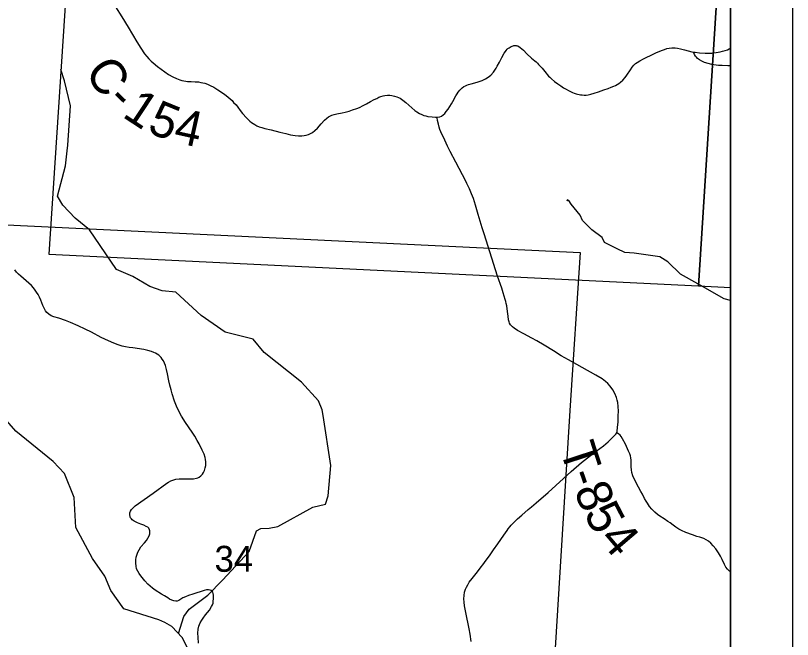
# Model space of a CAD drawing. Extents: x 0 to 34, y 0 to 22.
# Drawn here: x 29.485 to 30.737, y 17.697 to 18.702 of the extents above; entities that cross this region are included whole.
import ezdxf

# ---------------------------------------------------------------- set-up
doc = ezdxf.new("R2010")
doc.units = 0
for name, color, linetype in [('GM_X_County_Road', 7, 'Continuous'), ('GM_X_County_Road_Text', 7, 'Continuous'), ('GM_X_County_Text', 7, 'Continuous'), ('GM_X_Minor_River', 7, 'Continuous'), ('GM_X_Section', 7, 'Continuous'), ('GM_X_Section_Text', 7, 'Continuous'), ('GM_X_State_Shield', 7, 'Continuous'), ('GM_X_Township_Road', 7, 'Continuous'), ('GM_X_Township_Road_Text', 7, 'Continuous'), ('SH_Cut_Line', 7, 'Continuous'), ('SH_Data', 7, 'Continuous')]:
    doc.layers.add(name, color=color, linetype=linetype)

msp = doc.modelspace()

# ---------------------------------------------------------------- linework, layer by layer
at = {"layer": 'GM_X_County_Road'}
for points in [[(29.6461, 18.7166), (29.6563, 18.7004), (29.6668, 18.6835), (29.6739, 18.6718), (29.6808, 18.66), (29.687, 18.65), (29.6933, 18.6407), (29.6967, 18.6364), (29.7002, 18.6325), (29.7036, 18.6289), (29.7068, 18.626), (29.714, 18.6204), (29.7197, 18.6161), (29.732, 18.6077), (29.7389, 18.6037), (29.7444, 18.601), (29.7501, 18.5987), (29.7533, 18.5978), (29.7563, 18.5972), (29.7595, 18.5967), (29.7625, 18.5964), (29.7683, 18.5961), (29.7749, 18.5958), (29.7801, 18.5954), (29.7836, 18.5948), (29.787, 18.5942), (29.7905, 18.5933), (29.7946, 18.5917), (29.7991, 18.5896), (29.8046, 18.5868), (29.8111, 18.583), (29.8219, 18.5756), (29.8279, 18.5708), (29.8341, 18.5654), (29.8367, 18.5625), (29.8406, 18.5585), (29.8435, 18.5548), (29.8472, 18.5496), (29.8511, 18.5445), (29.8572, 18.5374), (29.8599, 18.5348), (29.8628, 18.5322), (29.8655, 18.53), (29.8706, 18.5266), (29.8741, 18.5248), (29.878, 18.5233), (29.8822, 18.5219), (29.8871, 18.5206), (29.8971, 18.5182), (29.9109, 18.5147), (29.9208, 18.5121), (29.9285, 18.5102), (29.9321, 18.5095), (29.9361, 18.5089), (29.9412, 18.5086), (29.9466, 18.5086), (29.9502, 18.509), (29.9538, 18.5097), (29.9573, 18.5109), (29.9604, 18.5122), (29.9637, 18.5141), (29.9676, 18.5171), (29.9719, 18.5212), (29.978, 18.5279), (29.983, 18.5336), (29.9867, 18.537), (29.9894, 18.5391), (29.9919, 18.5405), (29.995, 18.5418), (29.9986, 18.5429), (30.0032, 18.5438), (30.0114, 18.5455), (30.0165, 18.5467), (30.0227, 18.5484), (30.0285, 18.5504), (30.035, 18.5527), (30.0393, 18.5545), (30.0454, 18.5573), (30.0509, 18.5602), (30.0575, 18.5638), (30.0632, 18.5669), (30.0672, 18.569), (30.0706, 18.5708), (30.0738, 18.5722), (30.0775, 18.5732), (30.0806, 18.5738), (30.0844, 18.5742), (30.0883, 18.5742), (30.0918, 18.5737), (30.0957, 18.5728), (30.0997, 18.5716), (30.1022, 18.5706), (30.1049, 18.5691), (30.1095, 18.5661), (30.1142, 18.5624), (30.1238, 18.5536), (30.1288, 18.5495), (30.1321, 18.5472), (30.136, 18.5447), (30.1399, 18.5428), (30.1433, 18.5415), (30.1464, 18.5406), (30.1499, 18.5399), (30.1566, 18.539), (30.1621, 18.5385), (30.1645, 18.5386)], [(30.1645, 18.5386), (30.1653, 18.5386), (30.169, 18.5394), (30.1715, 18.5405), (30.1742, 18.5422), (30.1768, 18.5446), (30.1794, 18.5476), (30.1824, 18.5516), (30.1852, 18.5559), (30.1877, 18.56), (30.1899, 18.5637), (30.1947, 18.5729), (30.1968, 18.5761), (30.1987, 18.5792), (30.201, 18.582), (30.2031, 18.5842), (30.2052, 18.5861), (30.2079, 18.588), (30.2102, 18.5893), (30.2124, 18.5902), (30.2152, 18.5911), (30.2197, 18.5925), (30.2253, 18.594), (30.2307, 18.5955), (30.237, 18.5979), (30.2425, 18.6006), (30.2466, 18.6031), (30.2509, 18.6065), (30.2555, 18.6114), (30.2596, 18.6174), (30.2615, 18.6209), (30.265, 18.6272), (30.2689, 18.6348), (30.2728, 18.6419), (30.2747, 18.6447), (30.276, 18.6464), (30.2775, 18.6482), (30.2788, 18.6493), (30.2805, 18.6507), (30.2821, 18.6517), (30.2838, 18.6527), (30.2853, 18.6533), (30.2869, 18.6538), (30.2882, 18.654), (30.2896, 18.6541), (30.2907, 18.6541), (30.2918, 18.6541), (30.2932, 18.6539), (30.2947, 18.6534), (30.2964, 18.6525), (30.2983, 18.6512), (30.3009, 18.6489), (30.3037, 18.6465), (30.3094, 18.6406), (30.3168, 18.634), (30.3221, 18.6294), (30.3241, 18.6278), (30.3262, 18.6257), (30.3282, 18.6238), (30.3311, 18.6206), (30.3339, 18.6176), (30.3384, 18.6121), (30.3443, 18.6049), (30.3461, 18.603), (30.349, 18.6003), (30.3536, 18.5964), (30.359, 18.5923), (30.3638, 18.5891), (30.3682, 18.5862), (30.3725, 18.5837), (30.3763, 18.5817), (30.3829, 18.5785), (30.3857, 18.5774), (30.3886, 18.5765), (30.3908, 18.5758), (30.3934, 18.5753), (30.3959, 18.5749), (30.3986, 18.5747), (30.4016, 18.5744), (30.4047, 18.5744), (30.4081, 18.5747), (30.4102, 18.5751), (30.4125, 18.5756), (30.4179, 18.5773), (30.4247, 18.5796), (30.4334, 18.5826), (30.4403, 18.5851), (30.4449, 18.5868), (30.4496, 18.5887), (30.452, 18.5898), (30.4547, 18.5913), (30.4574, 18.5929), (30.4599, 18.5949), (30.4639, 18.5984), (30.4675, 18.6025), (30.4705, 18.6064), (30.4763, 18.6151), (30.4789, 18.6191), (30.4815, 18.6225), (30.4845, 18.625), (30.487, 18.627), (30.4912, 18.6295), (30.4972, 18.6326), (30.5015, 18.6346), (30.5097, 18.6386), (30.517, 18.6422), (30.5262, 18.6462), (30.5312, 18.648), (30.5349, 18.6491), (30.5387, 18.6499), (30.5429, 18.6504), (30.548, 18.6502), (30.5517, 18.6498), (30.5569, 18.6488), (30.563, 18.6473), (30.5691, 18.6457), (30.575, 18.6442), (30.578, 18.6437), (30.5802, 18.6433), (30.5872, 18.6426), (30.5967, 18.642), (30.6013, 18.642), (30.6074, 18.6421), (30.6141, 18.6427), (30.6205, 18.6439), (30.6247, 18.6448), (30.6288, 18.6459), (30.6323, 18.6472), (30.6352, 18.6487), (30.6372, 18.6499)]]:
    msp.add_lwpolyline(points, dxfattribs=at)
at = {"layer": 'GM_X_County_Text'}
msp.add_lwpolyline([(29.4304, 15.2876), (29.5713, 15.2568), (29.7749, 15.1808), (30.0202, 15.1042), (30.4162, 15.0021), (30.5527, 14.9001), (30.6372, 14.8869), (30.6372, 20.3098), (29.547, 20.3639), (28.6062, 20.4055)], dxfattribs=at)
at = {"layer": 'GM_X_Minor_River'}
for points in [[(29.7477, 17.7063), (29.7563, 17.7339), (29.765, 17.7458), (29.7951, 17.7684), (29.8189, 17.7927), (29.8615, 17.8384), (29.8735, 17.8722), (29.8804, 17.8758), (29.8937, 17.8765), (29.9077, 17.8787), (29.9642, 17.9103), (29.9848, 17.915), (29.989, 17.9285), (29.9935, 17.9773), (29.9808, 18.0579), (29.9792, 18.067), (29.9732, 18.0813), (29.9458, 18.1118), (29.886, 18.1596), (29.8681, 18.1811), (29.8231, 18.192), (29.7842, 18.2191), (29.7434, 18.2564), (29.7216, 18.259), (29.7014, 18.2657), (29.6742, 18.2818), (29.6481, 18.2933), (29.6047, 18.3573), (29.5815, 18.3759), (29.5617, 18.397), (29.5527, 18.4114), (29.5659, 18.4603), (29.5685, 18.4845), (29.5695, 18.4936), (29.5737, 18.5569), (29.564, 18.5971), (29.5585, 18.6155)], [(30.6372, 18.2433), (30.6271, 18.2459), (30.5847, 18.2701), (30.5567, 18.2856), (30.5363, 18.3053), (30.5234, 18.3137), (30.4822, 18.3197), (30.4671, 18.3208), (30.455, 18.3264), (30.4505, 18.3287), (30.4342, 18.3366), (30.4304, 18.345), (30.4141, 18.3571), (30.399, 18.3719), (30.3952, 18.381), (30.3808, 18.3985), (30.377, 18.4045), (30.3744, 18.4038), (30.3755, 18.4064)], [(29.7666, 17.6748), (29.7537, 17.6999), (29.7373, 17.7175), (29.7257, 17.7243), (29.7164, 17.7284), (29.6599, 17.7461), (29.6389, 17.7757), (29.6293, 17.7988), (29.6094, 17.8275), (29.5822, 17.8773), (29.5795, 17.9256), (29.5644, 17.9641), (29.5458, 17.9837), (29.486, 18.0327), (29.4484, 18.0749)]]:
    msp.add_lwpolyline(points, dxfattribs=at)
at = {"layer": 'GM_X_Section'}
msp.add_lwpolyline([(30.3951, 18.3204), (30.3786, 18.0661), (30.3627, 17.8138), (30.3475, 17.5607), (30.331, 17.3066), (30.2563, 17.3105), (30.177, 17.3146), (30.0998, 17.3186), (30.0187, 17.3227), (29.9382, 17.3269), (29.8591, 17.3308), (29.7781, 17.3351), (29.6912, 17.3401), (29.6192, 17.3436), (29.5335, 17.3481), (29.4508, 17.3523), (29.3695, 17.3565), (29.2849, 17.3606), (29.3481, 18.3713)], close=True, dxfattribs=at)
at = {"layer": 'GM_X_State_Shield'}
for points in [[(30.6372, 19.0797), (30.6372, 19.3091), (29.6072, 19.3563), (29.5388, 18.3179), (30.5859, 18.267)], [(30.6372, 18.2643), (30.6372, 19.0797), (30.5859, 18.267)]]:
    msp.add_lwpolyline(points, close=True, dxfattribs=at)
at = {"layer": 'GM_X_Township_Road'}
for points in [[(30.6372, 18.6214), (30.633, 18.6214), (30.6237, 18.6219), (30.6182, 18.6222), (30.6141, 18.6226), (30.6074, 18.6236), (30.6014, 18.625), (30.5956, 18.6269), (30.5911, 18.629), (30.5875, 18.6313), (30.5843, 18.6335), (30.5824, 18.6352), (30.581, 18.637), (30.5796, 18.6396), (30.578, 18.6437)], [(30.2775, 17.8726), (30.2793, 17.8752), (30.282, 17.8786), (30.284, 17.8809), (30.2865, 17.8837), (30.2908, 17.8882), (30.2939, 17.8912), (30.301, 17.8973), (30.3114, 17.9061), (30.3166, 17.9105), (30.3241, 17.917), (30.3433, 17.9338), (30.3808, 17.9674), (30.3975, 17.9821), (30.4071, 17.9896), (30.4211, 18.0004), (30.4325, 18.009), (30.4402, 18.0153), (30.4446, 18.0196), (30.4495, 18.0246), (30.4524, 18.0279), (30.4542, 18.0301), (30.4548, 18.0327), (30.4554, 18.0383), (30.4561, 18.0475), (30.4566, 18.0571), (30.4569, 18.065), (30.4565, 18.0721), (30.4557, 18.0787), (30.4548, 18.0828), (30.4535, 18.0868), (30.4509, 18.0933), (30.4477, 18.0994), (30.4436, 18.105), (30.4399, 18.1092), (30.4359, 18.1129), (30.4303, 18.1168), (30.4204, 18.123), (30.3982, 18.1354), (30.3897, 18.1401), (30.3761, 18.1475), (30.3645, 18.1542), (30.3519, 18.162), (30.337, 18.1711), (30.3253, 18.178), (30.3171, 18.1825), (30.3046, 18.1892), (30.2942, 18.1948), (30.2887, 18.1985), (30.2859, 18.2005), (30.2829, 18.2038), (30.2812, 18.2065), (30.2805, 18.2089), (30.2798, 18.2123), (30.279, 18.2177), (30.278, 18.2256), (30.2767, 18.2345), (30.276, 18.2384), (30.2753, 18.2418), (30.2744, 18.2449), (30.2727, 18.2504), (30.271, 18.2557), (30.2687, 18.2629), (30.262, 18.2824), (30.2402, 18.3504), (30.2371, 18.3602), (30.2308, 18.3816), (30.2264, 18.3968), (30.223, 18.4078), (30.2202, 18.4149), (30.2167, 18.423), (30.2124, 18.432), (30.2086, 18.4396), (30.2056, 18.4456), (30.195, 18.4661), (30.1858, 18.4834), (30.1815, 18.4922), (30.1769, 18.5016), (30.1708, 18.515), (30.1692, 18.5189), (30.168, 18.5225), (30.1668, 18.5272), (30.1654, 18.5335), (30.1647, 18.5376), (30.1645, 18.5386)], [(29.7803, 17.6907), (29.7794, 17.7006), (29.7792, 17.7072), (29.7795, 17.7135), (29.7806, 17.7183), (29.7815, 17.721), (29.7828, 17.7237), (29.7853, 17.728), (29.7876, 17.7312), (29.7915, 17.7364), (29.7977, 17.7443), (29.801, 17.75), (29.8028, 17.7529), (29.8035, 17.7553), (29.8039, 17.7583), (29.8042, 17.7627), (29.8043, 17.7664), (29.8041, 17.7684), (29.8038, 17.7709), (29.803, 17.773), (29.8019, 17.7746), (29.8006, 17.7757), (29.7991, 17.7764), (29.7961, 17.7769), (29.793, 17.7766), (29.7893, 17.7757), (29.771, 17.7701), (29.7642, 17.7676), (29.7591, 17.7657), (29.7548, 17.7639), (29.7482, 17.7596), (29.7458, 17.7587), (29.7433, 17.7584), (29.7402, 17.7589), (29.7371, 17.7601), (29.7332, 17.762), (29.7307, 17.7639), (29.7254, 17.7673), (29.7204, 17.7701), (29.7105, 17.7761), (29.7059, 17.7798), (29.6985, 17.7861), (29.6938, 17.7914), (29.6874, 17.7995), (29.6846, 17.8031), (29.6822, 17.8069), (29.6804, 17.8107), (29.6796, 17.8149), (29.6789, 17.8201), (29.6791, 17.8253), (29.6796, 17.8294), (29.6811, 17.8346), (29.6823, 17.8377), (29.6843, 17.8415), (29.6873, 17.8461), (29.6929, 17.8527), (29.6962, 17.8565), (29.6987, 17.8601), (29.7007, 17.864), (29.7016, 17.8669), (29.7019, 17.8695), (29.7016, 17.8719), (29.7012, 17.8738), (29.7001, 17.876), (29.6983, 17.8778), (29.696, 17.879), (29.6919, 17.8809), (29.6872, 17.8827), (29.682, 17.8846), (29.6763, 17.8876), (29.6731, 17.8899), (29.6719, 17.8913), (29.6707, 17.8927), (29.6699, 17.8947), (29.6695, 17.8982), (29.6697, 17.901), (29.6707, 17.9036), (29.6723, 17.9065), (29.6745, 17.9086), (29.6782, 17.9121), (29.7068, 17.9327), (29.7293, 17.9489), (29.7318, 17.9505), (29.7353, 17.9523), (29.7386, 17.9537), (29.7435, 17.9552), (29.749, 17.9558), (29.757, 17.9558), (29.7665, 17.9557), (29.7721, 17.9559), (29.7766, 17.9567), (29.7788, 17.9573), (29.781, 17.9585), (29.7841, 17.9607), (29.7865, 17.9634), (29.788, 17.9661), (29.7896, 17.9693), (29.791, 17.9735), (29.7917, 17.9775), (29.792, 17.9834), (29.7916, 17.9868), (29.7909, 17.9901), (29.7891, 17.9953), (29.7861, 18.0021), (29.7812, 18.0123), (29.7782, 18.0176), (29.7742, 18.0243), (29.7698, 18.0312), (29.7589, 18.0466), (29.7527, 18.0567), (29.7473, 18.0669), (29.7446, 18.0727), (29.7413, 18.0811), (29.7376, 18.0929), (29.7358, 18.0994), (29.734, 18.1066), (29.7325, 18.1136), (29.7303, 18.1248), (29.7287, 18.1321), (29.7269, 18.1382), (29.7253, 18.1423), (29.7235, 18.1457), (29.7215, 18.1489), (29.7197, 18.1513), (29.7162, 18.155), (29.7137, 18.1569), (29.711, 18.1585), (29.7083, 18.1596), (29.7046, 18.161), (29.6987, 18.1627), (29.6918, 18.1644), (29.6744, 18.1668), (29.6681, 18.1677), (29.6625, 18.1685), (29.6571, 18.1698), (29.6508, 18.1717), (29.6435, 18.1743), (29.6351, 18.178), (29.6232, 18.1837), (29.6079, 18.192), (29.5977, 18.1968), (29.5864, 18.2021), (29.5737, 18.2077), (29.5657, 18.2111), (29.5549, 18.2145), (29.5471, 18.2168), (29.5427, 18.2186), (29.5387, 18.2209), (29.5356, 18.2239), (29.5333, 18.2267), (29.5319, 18.2296), (29.5294, 18.2351), (29.5259, 18.2439), (29.5238, 18.2486), (29.5215, 18.2529), (29.5193, 18.2564), (29.5168, 18.2601), (29.5141, 18.2635), (29.5109, 18.2674), (29.5068, 18.2714), (29.5025, 18.2751), (29.4939, 18.2824), (29.4902, 18.2856), (29.4869, 18.2891), (29.4843, 18.2926)], [(30.6372, 17.8057), (30.6357, 17.8068), (30.6327, 17.8099), (30.6301, 17.8134), (30.6275, 17.8177), (30.6237, 17.8259), (30.6212, 17.8311), (30.6181, 17.8366), (30.6137, 17.843), (30.6096, 17.8479), (30.6058, 17.8522), (30.6018, 17.8554), (30.5983, 17.8577), (30.5945, 17.8594), (30.5914, 17.8606), (30.5879, 17.8616), (30.5832, 17.8628), (30.5761, 17.8655), (30.5654, 17.8695), (30.5585, 17.8724), (30.5539, 17.8747), (30.5493, 17.8778), (30.5448, 17.8811), (30.54, 17.8847), (30.5364, 17.8871), (30.5304, 17.8912), (30.5236, 17.8957), (30.5199, 17.8983), (30.5155, 17.902), (30.5106, 17.9071), (30.507, 17.9114), (30.5035, 17.9165), (30.5012, 17.92), (30.499, 17.9243), (30.4954, 17.9309), (30.4931, 17.9353), (30.4893, 17.9424), (30.4829, 17.9545), (30.4802, 17.9607), (30.4785, 17.966), (30.4778, 17.9703), (30.4774, 17.9752), (30.4773, 17.9814), (30.4771, 17.9857), (30.4768, 17.9895), (30.4761, 17.9926), (30.4749, 17.9961), (30.4732, 18.0004), (30.468, 18.0116), (30.4634, 18.02), (30.4614, 18.0239), (30.4596, 18.0264), (30.457, 18.0283), (30.4542, 18.0301)], [(30.2197, 17.6935), (30.2178, 17.7056), (30.2164, 17.7138), (30.2108, 17.7405), (30.2089, 17.7508), (30.208, 17.7568), (30.2077, 17.7622), (30.208, 17.7677), (30.2089, 17.7731), (30.2105, 17.7778), (30.212, 17.7814), (30.214, 17.785), (30.2165, 17.7891), (30.2209, 17.795), (30.2296, 17.8061), (30.2357, 17.8139), (30.2383, 17.8173), (30.2438, 17.8245), (30.2488, 17.8315), (30.2556, 17.8411), (30.2627, 17.8512), (30.2721, 17.865), (30.2775, 17.8726)]]:
    msp.add_lwpolyline(points, dxfattribs=at)
at = {"layer": 'SH_Cut_Line'}
msp.add_lwpolyline([(29.4304, 15.2876), (29.5713, 15.2568), (29.7749, 15.1808), (30.0202, 15.1042), (30.4162, 15.0021), (30.5527, 14.9001), (30.6372, 14.8869), (30.6372, 20.9), (23.8372, 20.9)], dxfattribs=at)
at = {"layer": 'SH_Data'}
for points in [[(23.7372, 21), (30.7372, 21), (30.7372, 14), (23.7372, 14)], [(23.8372, 20.9), (30.6372, 20.9), (30.6372, 14.1), (23.8372, 14.1)]]:
    msp.add_lwpolyline(points, close=True, dxfattribs=at)

# ---------------------------------------------------------------- texts
at = {"layer": 'GM_X_County_Road_Text'}
for s, rotation, p in [('C', 304.4998, (29.5954, 18.6115)), ('-', 316.1355, (29.63, 18.5635)), ('1', 326.5173, (29.6556, 18.5403)), ('5', 337.7555, (29.6955, 18.5153)), ('4', 347.5203, (29.738, 18.4989))]:
    msp.add_text(s, height=0.0568, rotation=rotation, dxfattribs=at).set_placement(p)
at = {"layer": 'GM_X_Section_Text'}
msp.add_text('34', height=0.04186, rotation=0, dxfattribs=at).set_placement((29.8059, 17.8059))
at = {"layer": 'GM_X_Township_Road_Text'}
for s, rotation, p in [('T', 288.1334, (30.3617, 18.0044)), ('-', 289.1162, (30.3752, 17.963)), ('8', 292.8593, (30.3843, 17.9371)), ('5', 297.6236, (30.4001, 17.9002)), ('4', 310.4716, (30.4241, 17.8577))]:
    msp.add_text(s, height=0.0568, rotation=rotation, dxfattribs=at).set_placement(p)

doc.saveas('drawing.dxf')
